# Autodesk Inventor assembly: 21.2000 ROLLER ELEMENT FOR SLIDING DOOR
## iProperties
Created: 2007-05
Part Number: 21.2000 ROLLER ELEMENT FOR SLIDING DOOR
Document SubType Name: Assembly
Designer: Andy Moles
Author: Andy Moles
